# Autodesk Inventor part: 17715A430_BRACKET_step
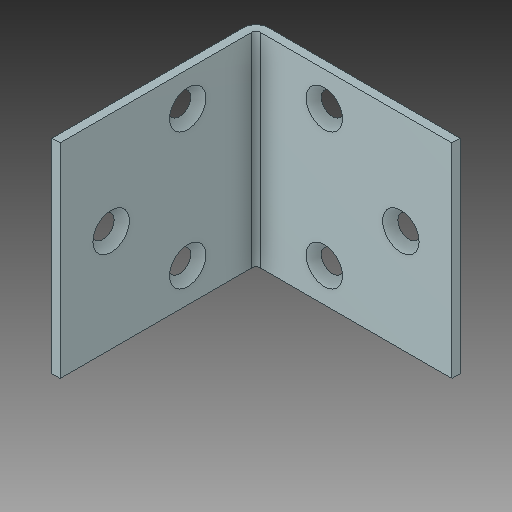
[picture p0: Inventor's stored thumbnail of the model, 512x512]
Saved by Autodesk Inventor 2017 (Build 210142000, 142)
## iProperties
Created: 2017-05
Part Number: 17715A430_BRACKET_step
Material: Generic
Document SubType Name: Modeling
Designer: Savy
Density: 1 g/cm^3
Appearance: Default
Mass: 4.07735 g
Surface Area: 58.9055 cm^2
Volume: 4.07735 cm^3
Author: Savy
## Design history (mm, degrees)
feature "SOLID1"
body "Solid1"
